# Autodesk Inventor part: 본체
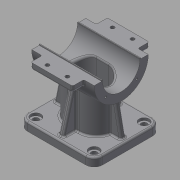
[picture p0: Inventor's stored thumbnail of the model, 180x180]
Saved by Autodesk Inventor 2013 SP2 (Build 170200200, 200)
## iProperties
Created: 2015-12
Part Number: 본체
Material: 일반
Document SubType Name: Modeling
Designer: mduedu
Density: 1 g/cm^3
Author: mduedu
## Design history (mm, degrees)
sketch "스케치1"
  geometry: L1 (45, 40)-(-45, 40); L2 (-45, 40)-(-45, -40); L3 (-45, -40)-(45, -40); L4 (45, -40)-(45, 40); L5 (45, 40)-(-45, -40); L6 (-45, 40)-(45, -40); 1 further point
  constraints: 12 end point, 2 midpoint, 2 parallel, 1 horizontal, 1 perpendicular
  dimensions: "d0" = 90 distance of L2.end L3.end; "d2" = 80 distance of L1.end L2.end
extrude "돌출1" new body sketch "스케치1" distance "d3" = 10; taper "d4" = 0 deg
sketch "스케치2"
  geometry: L1 (0, 40)-(0, -40) reference; C1 r 32.5 at (80, 0); 1 further point
  constraints: 1 centre point
  dimensions: "d5" = 65 diameter of C1; "d6" = 80 distance from line of C1.centre L1
extrude "돌출2" join sketch "스케치2" stored distance "d7" = 75; taper "d8" = 0 deg
sketch "스케치3"
  geometry: L1 (-27.5, -20)-(27.5, -20); L2 (27.5, -20)-(27.5, 20); L3 (27.5, 20)-(-27.5, 20); L4 (-27.5, 20)-(-27.5, -20); L5 (-27.5, -20)-(27.5, 20); L6 (27.5, -20)-(-27.5, 20); 1 further point
  constraints: 12 end point, 2 midpoint, 2 parallel, 1 horizontal, 1 perpendicular
  dimensions: "d9" = 55 distance of L2.end L3.end; "d11" = 40 distance of L1.end L2.end
extrude "돌출3" new body sketch "스케치3" stored distance "d12" = 75; taper "d13" = 0 deg
fillet "모깎기1"
fillet "모깎기2"
feature "결합1"
  node "솔리드2"
fillet "모깎기3" dims "d14" = 10
sketch "스케치4"
  geometry: L1 (-37.5, 47.5)-(37.5, 47.5) reference; L2 (35, 10)-(45, 10) reference; L3 (32.5, 47.5)-(40, 10); L4 (37.5, 47.5)-(37.5, 112.5) reference; L5 (45, 10)-(45, 0) reference; 1 further point
  constraints: 2 end point, 1 midpoint, 1 point on line
  dimensions: "d15" = 5 distance from line of L3.start L4; "d16" = 5 distance from line of L3.end L5
sketch "스케치5"
  geometry: L1 (10, 40)-(10, 30) reference; L2 (10, 35)-(56.569, 22.522); L3 (0, 40)-(10, 40) reference; 2 further points
  constraints: 2 end point, 1 midpoint, 2 other
  dimensions: "d17" = 5 distance from line of L2.start L3; "d18" = 15 deg angle of L2 L3
feature "리브1" dims "d19" = 1, "d20" = 6, "d21" = 0, "d22" = 0, "d23" = 1, "d24" = 1
feature "리브2" dims "d25" = 1, "d26" = 6, "d27" = 0, "d28" = 0, "d29" = 1, "d30" = 1
fillet "모깎기4" dims "d31" = 2
fillet "모깎기5" dims "d32" = 2
fillet "모깎기6" dims "d33" = 2
sketch "스케치6"
  geometry: A1 r 10 centre (-35, 30) between (-35, 40) and (-45, 30) reference; A2 r 10 centre (35, 30) between (45, 30) and (35, 40) reference; A3 r 10 centre (35, -30) between (35, -40) and (45, -30) reference; A4 r 10 centre (-35, -30) between (-45, -30) and (-35, -40) reference; 5 further points
  constraints: 4 coincident
hole "구멍1" sketch "스케치6" at (-35, 30), (35, 30), (35, -30), (-35, -30) diameter "d34" = 7; stored, may be unused: countersink angle "d38" = 90 deg, drill point angle "d40" = 118 deg; dims "d35" = 6, "d36" = 12, "d37" = 3, "d39" = 8
fillet "모깎기7" dims "d41" = 2
hole "구멍2" diameter "d44" = 45; stored, may be unused: countersink angle "d48" = 90 deg, drill point angle "d50" = 118 deg; dims "d42" = 10, "d43" = 10, "d45" = 6, "d46" = 4, "d47" = 2, "d49" = 8
sketch "스케치7" dims "d52" = 26.5
  geometry: L1 (0, 0)-(32.5, 0); L2 (0, 0)-(22.981, 22.981); A1 r 32.5 centre (0, 0) between (32.5, 0) and (22.981, 22.981) reference; 3 further points
  constraints: 4 end point, 2 point on circle, 1 coincident, 1 horizontal, 1 point on line, 3 other
  dimensions: "d51" = 45 deg angle of L2 L1
hole "구멍3" sketch "스케치7" at (18.738, 18.738) diameter "d54" = 2.459; stored, may be unused: countersink angle "d58" = 90 deg, drill point angle "d60" = 118 deg; dims "d55" = 8, "d56" = 4, "d57" = 2, "d59" = 10
sketch "스케치8"
  geometry: L1 (72.5, 31.623)-(72.5, 46); L2 (72.5, 46)-(87.5, 46); L3 (87.5, 46)-(87.5, 31.623); A1 r 32.5 centre (80, 0) between (87.5, 31.623) and (72.5, 31.623) reference; 2 further points
  constraints: 6 end point, 2 point on circle, 1 midpoint, 1 parallel, 1 vertical, 1 vertical alignment
  dimensions: "d64" = 15 distance of L1.end L2.end; "d66" = 46 distance from line of L2 A1.centre
extrude "돌출4" join sketch "스케치8" stored distance "d67" = 50; taper "d68" = 0 deg
fillet "모깎기8" dims "d69" = 3
fillet "모깎기9" dims "d70" = 2
sketch "스케치9"
  geometry: L1 (-76, 82.5)-(76, 82.5); L2 (76, 82.5)-(76, 0); L3 (76, 0)-(-76, 0); L4 (-76, 0)-(-76, 82.5); L5 (-46, 4.5)-(-46, -4.5) reference; C1 r 32.5 at (0, 0) reference; 2 further points
  constraints: 8 end point, 2 parallel, 1 coincident, 1 horizontal, 1 midpoint, 1 perpendicular
  dimensions: "d71" = 50 distance edge to line of C1 L1; "d72" = 30 distance between parallel lines of L4 L5
extrude "돌출5" cut sketch "스케치9" stored distance "d73" = 0; taper "d74" = 0 deg
node "작업 평면1"
sketch "스케치10"
  geometry: L1 (-7.5, 15)-(7.5, 15); L2 (-7.5, -15)-(7.5, -15); A1 r 20 centre (-7.5, 0) between (-7.5, 20) and (-26.977, 4.545) reference; A2 r 20 centre (7.5, 0) between (26.977, 4.545) and (7.5, 20) reference; A3 r 15 centre (-7.5, 0) between (-7.5, 15) and (-7.5, -15); A4 r 15 centre (7.5, 0) between (7.5, -15) and (7.5, 15); 1 further point
  constraints: 7 point on circle, 4 end point, 4 tangent, 3 point on line, 2 centre point, 2 coincident, 1 horizontal
  dimensions: "d77" = 5 radial gap between concentric circles of A3 A1
extrude "돌출6" cut sketch "스케치10" stored distance "d78" = 50; taper "d79" = 0 deg
fillet "모깎기10" dims "d80" = 3
sketch "스케치11"
  geometry: 2 further points
  constraints: 1 coincident
hole "구멍4" sketch "스케치11" at (0, 0) diameter "d81" = 12; stored, may be unused: countersink angle "d85" = 90 deg, drill point angle "d87" = 118 deg; dims "d82" = 8, "d83" = 40, "d84" = 10, "d86" = 10
sketch "스케치12"
  geometry: C1 r 10 at (0, 0); 1 further point
  constraints: 1 centre point, 1 coincident
  dimensions: "d88" = 20 diameter of C1
extrude "돌출7" cut sketch "스케치12" distance "d89" = 5; taper "d90" = 0 deg
chamfer "모따기1" distance "d91" = 1; stored, may be unused: second distance "d92" = 2, angle "d93" = 45 deg
fillet "모깎기11" dims "d94" = 0.5
feature "립1" dims "d95" = 1, "d96" = 1, "d97" = 0, "d98" = 3 deg, "d99" = 3 deg, "d100" = 0
sketch "스케치13"
  geometry: 4 further points
hole "구멍5" sketch "스케치13" at (34, 5.936), (10, -72.269), (34, -72.269), (10, 5.936) diameter "d101" = 4.5; stored, may be unused: countersink angle "d105" = 90 deg, drill point angle "d107" = 0 deg; dims "d102" = 6, "d103" = 4, "d104" = 2, "d106" = 8
fillet "모깎기12" dims "d115" = 0.3
node "솔리드1"
mirror "대칭1"
mirror "대칭2"
pattern_circular "원형 패턴1" dims angle "d62" = 360 deg
mirror "대칭3"
mirror "대칭4"
